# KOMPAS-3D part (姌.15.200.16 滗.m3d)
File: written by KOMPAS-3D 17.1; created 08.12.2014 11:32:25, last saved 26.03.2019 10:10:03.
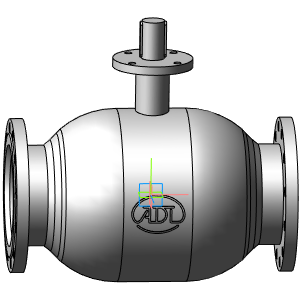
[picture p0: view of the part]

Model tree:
1. Операция без истории:4  (labels: Сталь 20  ГОСТ 1050-88)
